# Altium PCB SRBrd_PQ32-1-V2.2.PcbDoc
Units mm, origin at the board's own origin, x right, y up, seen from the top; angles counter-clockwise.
Board outline 34 x 34.84 mm, 4 copper layers (Top Layer, Signal Layer 1, Signal Layer 2, Bottom Layer), stack 1.02 mm thick; 24 components, 9 nets, 205 pads, 210 vias.
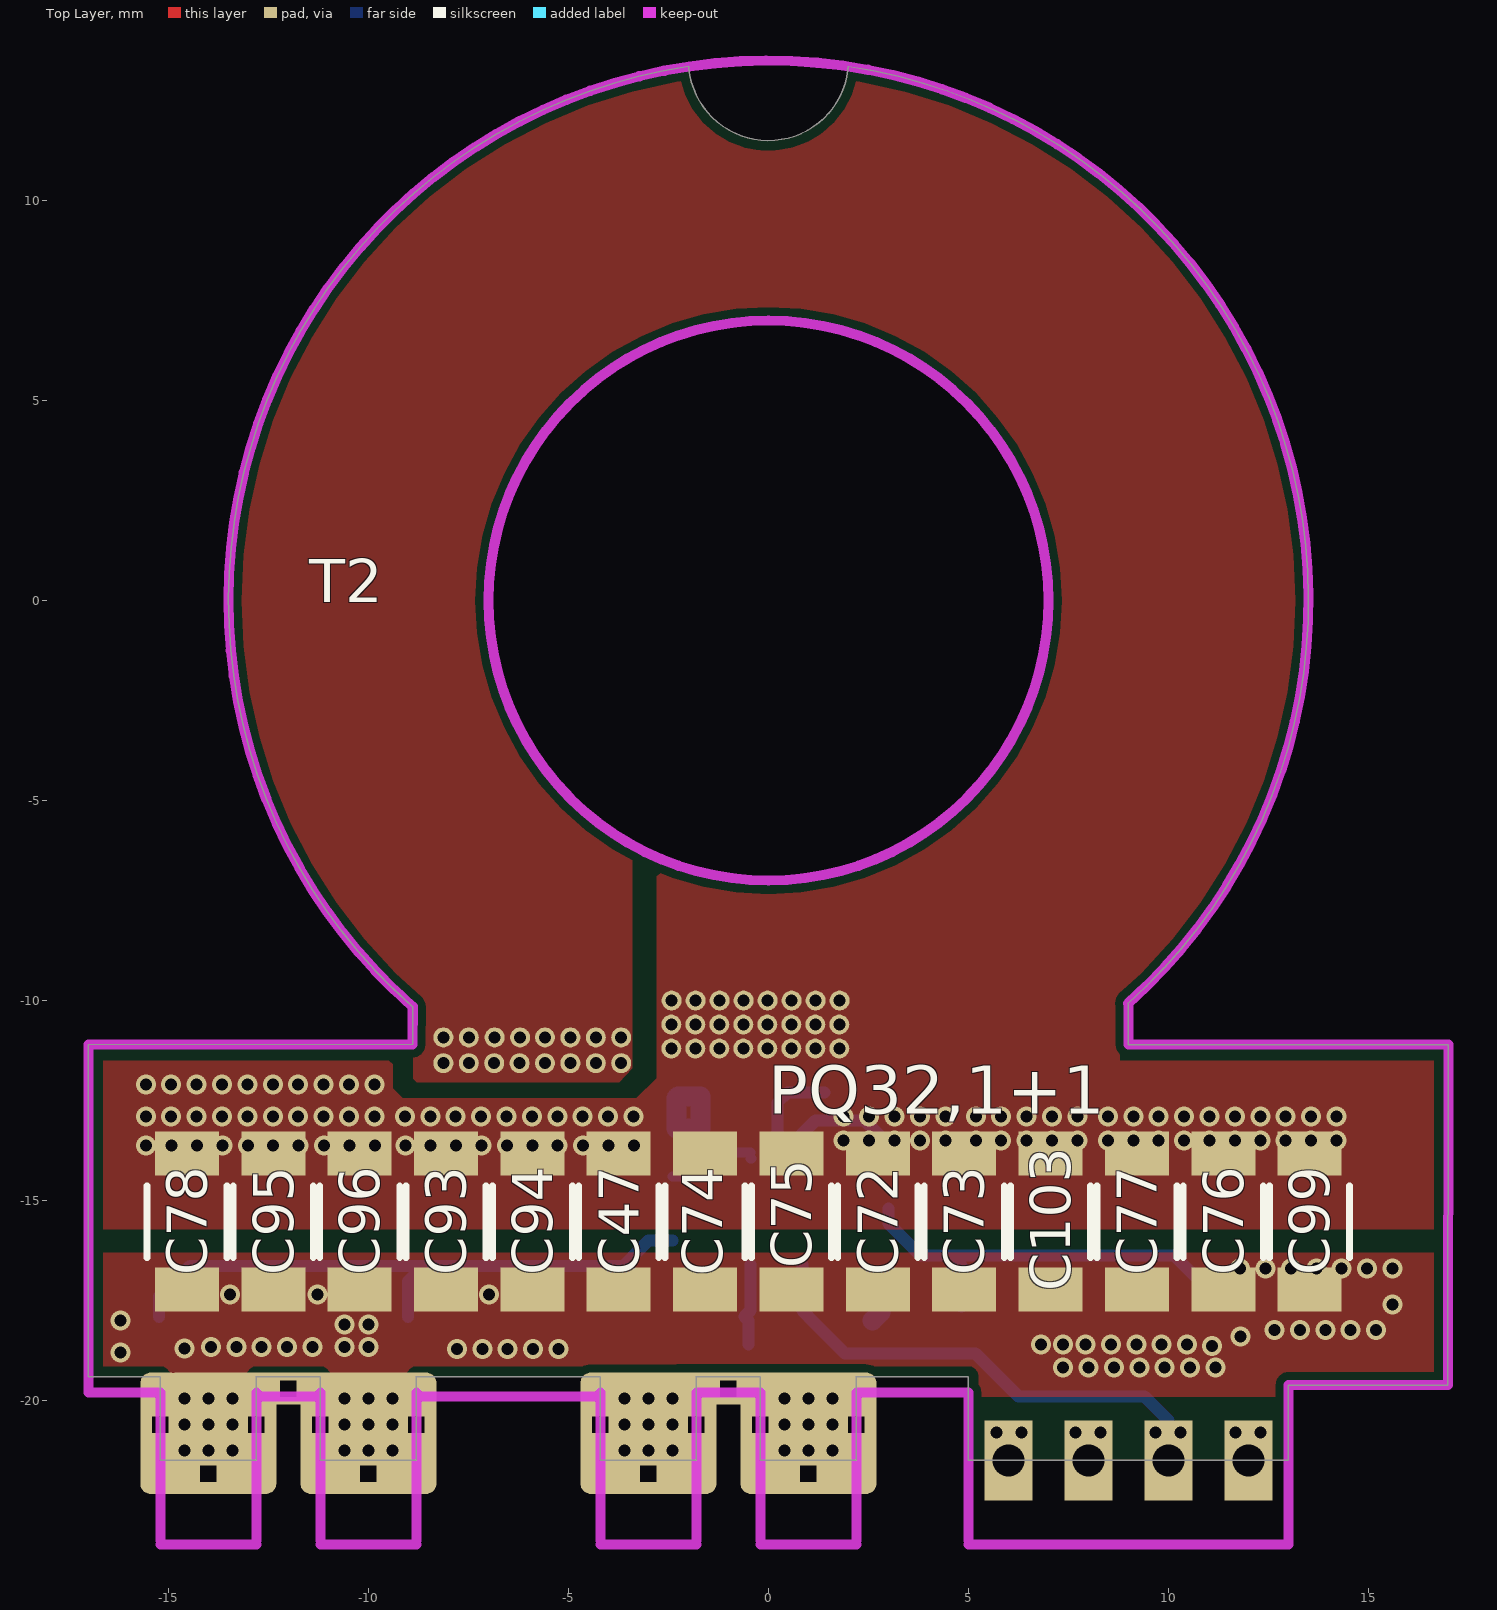
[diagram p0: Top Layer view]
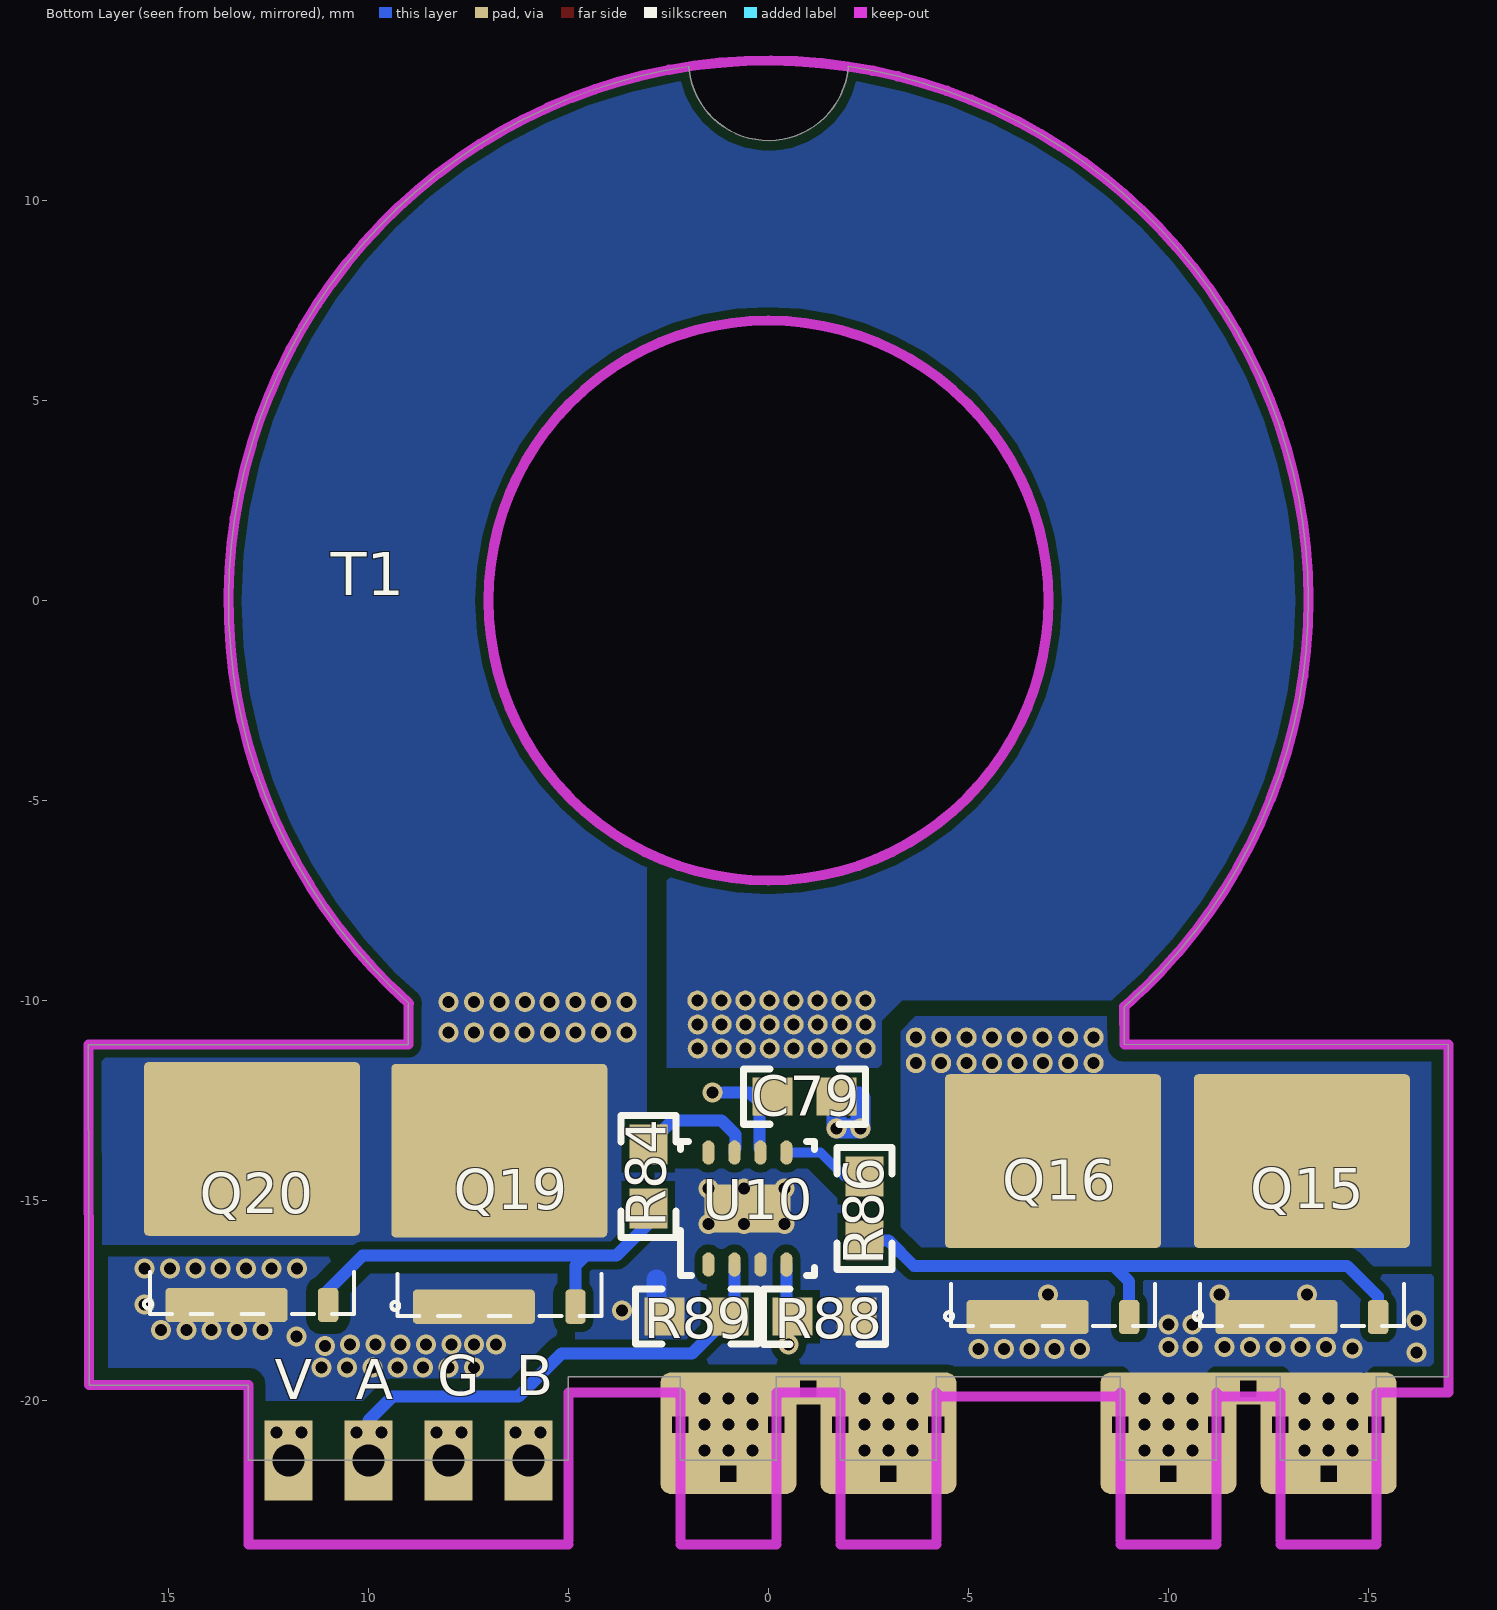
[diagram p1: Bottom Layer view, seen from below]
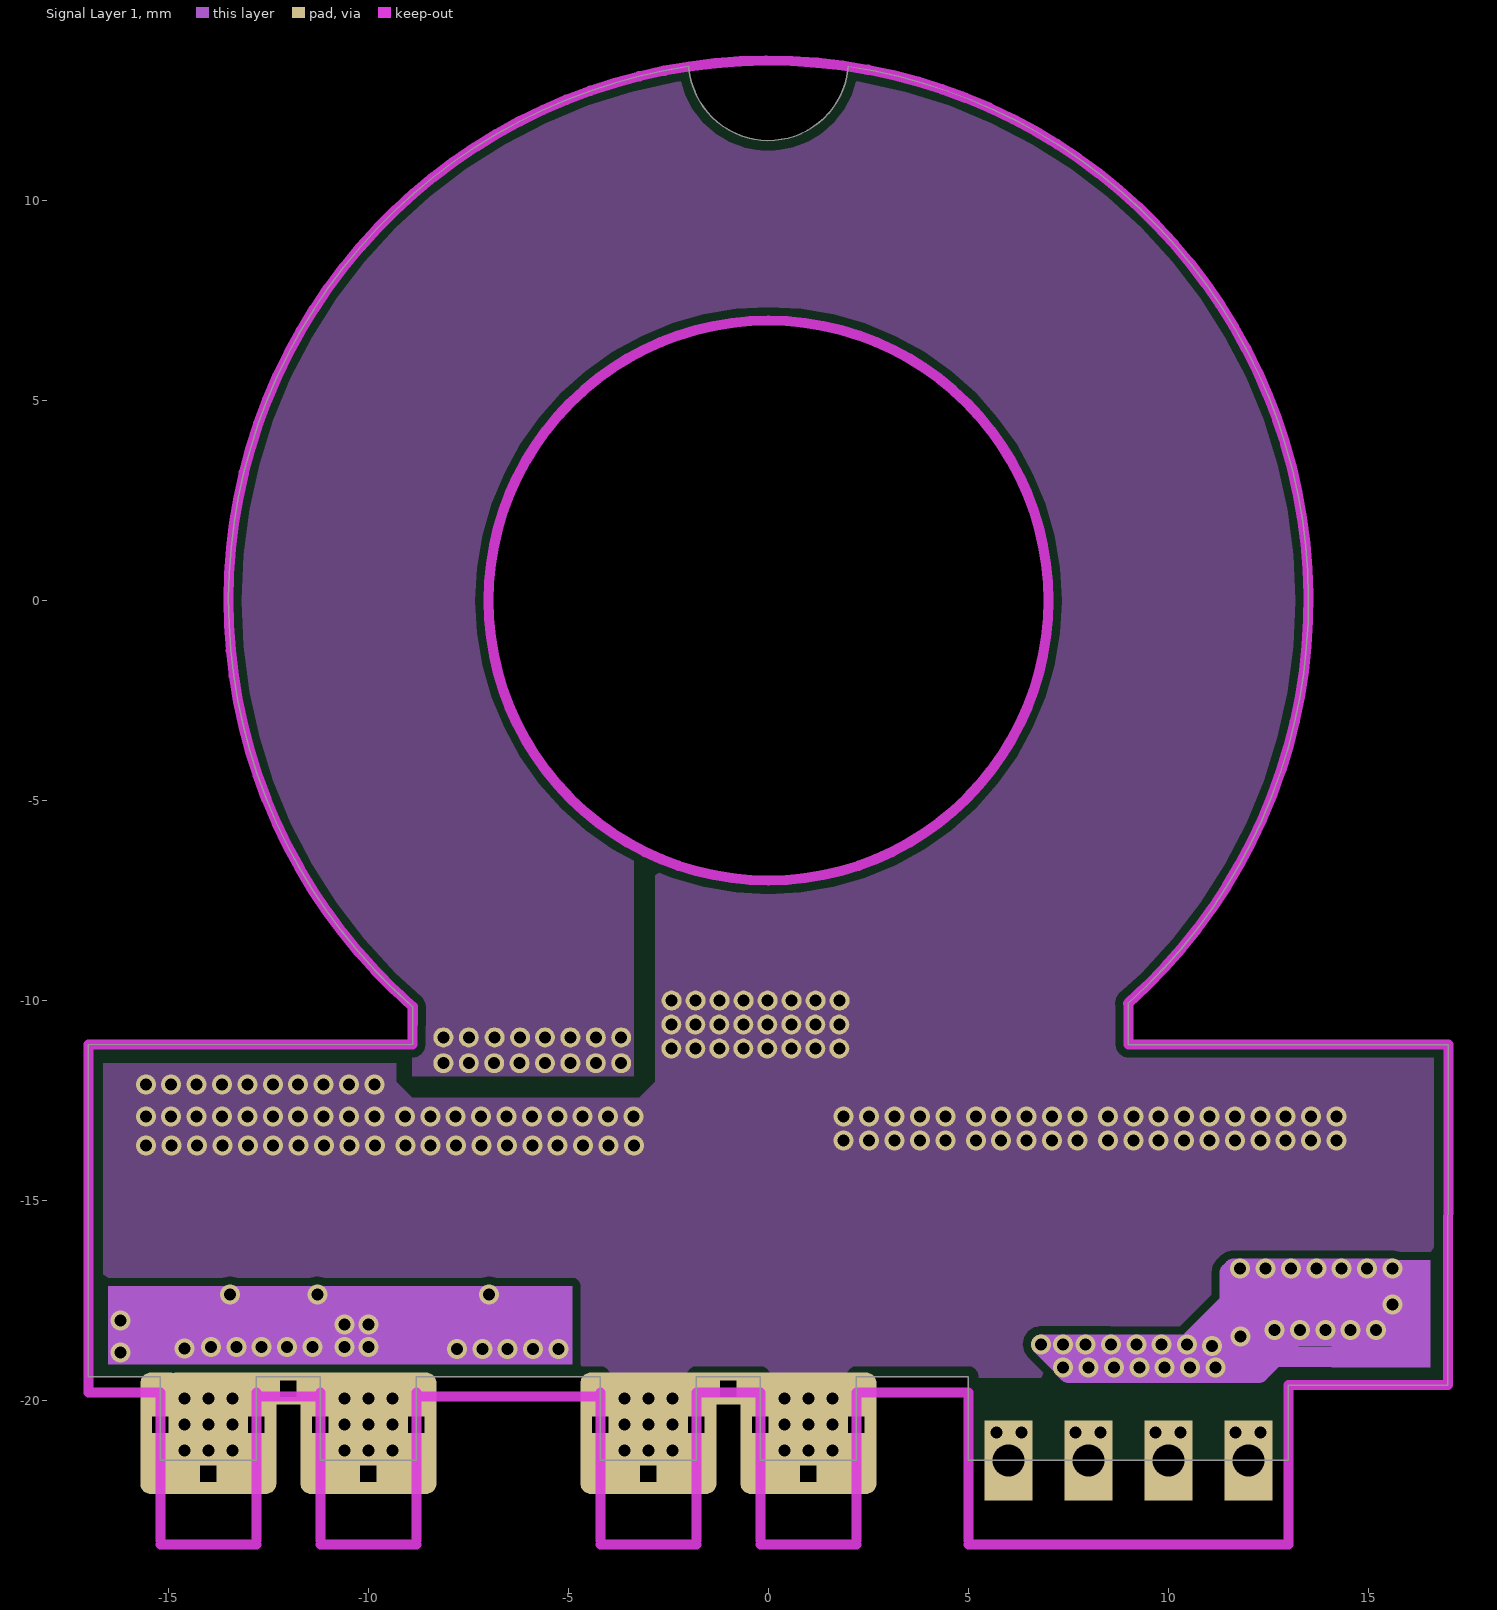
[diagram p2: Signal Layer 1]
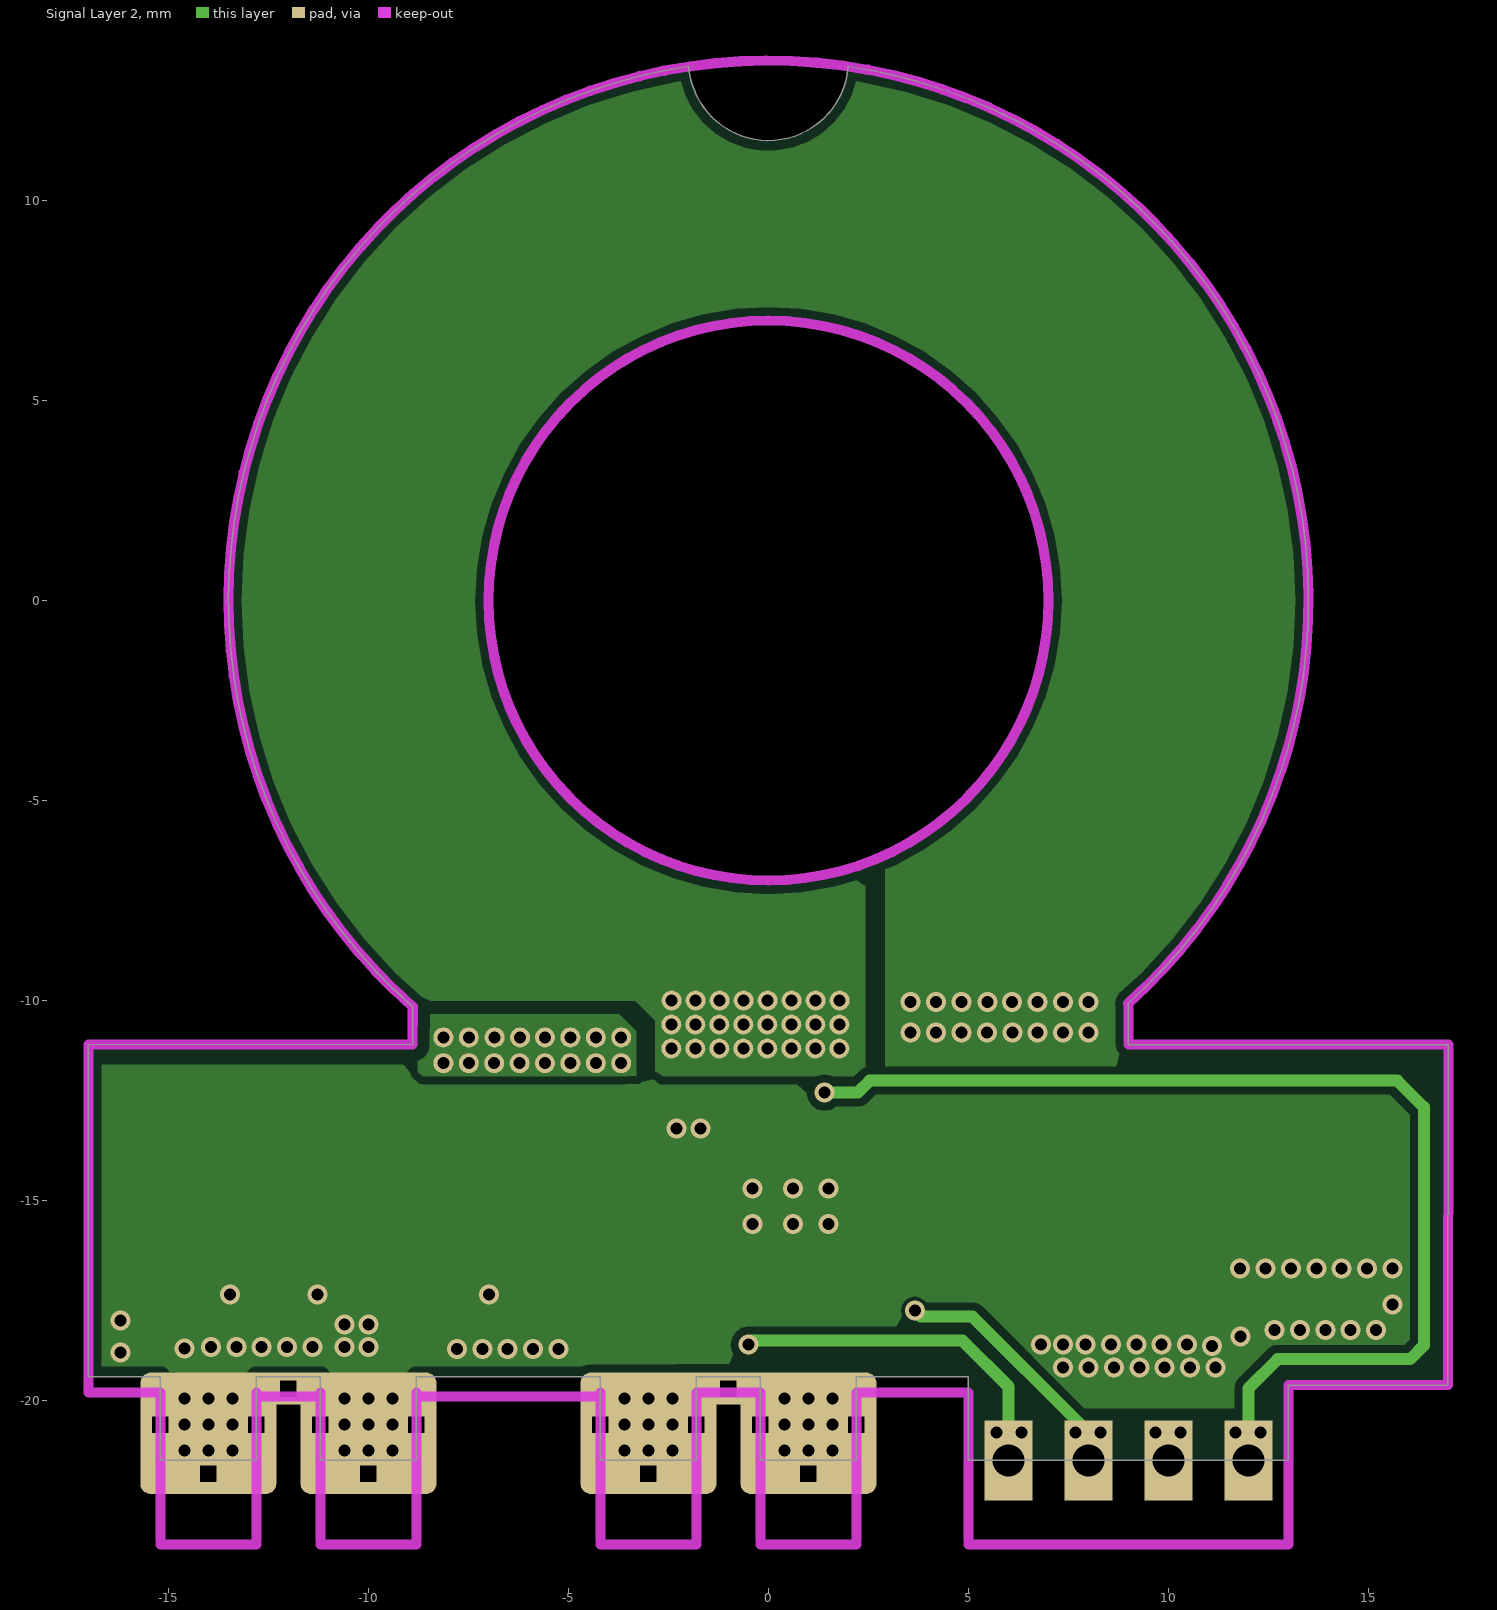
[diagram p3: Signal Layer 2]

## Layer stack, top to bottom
Top Solder: solder mask 0.0102, Solder Resist, Dk 3.5
Top Layer: signal copper 0.105
Dielectric 1: core 0.1, FR-4, Dk 4.2
Signal Layer 1: signal copper 0.105
Dielectric 3: prepreg 0.4, Dk 4.2
Signal Layer 2: signal copper 0.105
Dielectric 2: core 0.1, Dk 4.2
Bottom Layer: signal copper 0.105
Bottom Solder: solder mask 0.0102, Solder Resist, Dk 3.5

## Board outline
-15.2,-21.488 -12.8,-21.488 -12.8,-19.4 -11.2,-19.4 -11.2,-21.488 -8.8,-21.488 -8.8,-19.4 -4.2,-19.4 -4.2,-21.488 -1.8,-21.488 -1.8,-19.4 -0.2,-19.4 -0.2,-21.488 2.2,-21.488 2.2,-19.4 5,-19.4 5,-21.488 13,-21.488 13,-19.613 16.987,-19.613 17,-11.1 9,-11.1 9,-10.1 8.987,-10.074 ccw(c0,0) 1.999,13.351 1.986,13.264 cw(c0,13.5) -1.99,13.3 -1.997,13.351 ccw(c0,0) -8.925,-10.129 -8.895,-10.16 -8.895,-11.095 -17,-11.1 -17,-19.4 -15.2,-19.4

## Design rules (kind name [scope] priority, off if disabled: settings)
BoardOutlineClearance [All] p1: gap=0.254 ignorepadtopadclearanceinfootprint=FALSE except(0: Arc-SplitContinuation Track-SplitContinuation SMDPad-SplitContinuation THPad-SplitContinuation Via-SplitContinuation Fill-SplitContinuation Poly-SplitContinuation Region-SplitContinuation Text-SplitContinuation)
Clearance [All] p1: gap=0.2 ignorepadtopadclearanceinfootprint=FALSE
ComponentClearance [All] p1 off: gap=0.254 collisioncheckmode=3 verticalgap=0.254 showdistances=FALSE
Height [All] p1 off: minheight=0 maxheight=25.4 prefheight=12.7
HoleSize [All] p1: absolutevalues=TRUE maxlimit=30 minlimit=0.025 maxpercent=80.000 minpercent=20.000
MinimumSolderMaskSliver [All] p1: minsoldermaskwidth=0
PolygonConnect [All] p1: connectstyle=Direct reliefconductorwidth=0.254 reliefentries=4 polygonreliefangle="90 Angle" airgapwidth=0.254
RoutingVias [All] p1: holewidth=0.711 width=1.27 viastyle="Through Hole" minholewidth=0.711 minwidth=1.27 maxholewidth=0.711 maxwidth=1.27
SilkToSilkClearance [All] p1: silktosilkclearance=0
SilkToSolderMaskClearance [IsPad] p1: minsilkscreentomaskgap=0.1 clearancetoexposedcopper=TRUE
SolderMaskExpansion [All] p1: expansion=0.102 istentingtop=FALSE
Width [All] p1: maxlimit=2.54 minlimit=0.152 preferedwidth=0.254
24 further rules are at their usual default settings.

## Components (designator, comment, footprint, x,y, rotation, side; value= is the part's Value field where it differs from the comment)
C47 "GMK316AB7106KL-TR" 1206_190 -3.744,-15.529 r270 top value=10uF
C72 "GMK316AB7106KL-TR" 1206_190 2.733,-15.529 r270 top value=10uF
C73 "GMK316AB7106KL-TR" 1206_190 4.892,-15.529 r270 top value=10uF
C74 "GMK316AB7106KL-TR" 1206_190 -1.585,-15.529 r270 top value=10uF
C75 "GMK316AB7106KL-TR" 1206_190 0.574,-15.529 r270 top value=10uF
C76 "GMK316AB7106KL-TR" 1206_190 11.369,-15.529 r270 top value=10uF
C77 "GMK316AB7106KL-TR" 1206_190 9.21,-15.529 r90 top value=10uF
C78 "GMK316AB7106KL-TR" 1206_190 -14.539,-15.529 r90 top value=10uF
C79 "UMK107AB7105KA-T" 0603 -0.9,-12.4 r0 bottom value=1uF
C93 "GMK316AB7106KL-TR" 1206_190 -8.062,-15.529 r90 top value=10uF
C94 "GMK316AB7106KL-TR" 1206_190 -5.903,-15.529 r90 top value=10uF
C95 "GMK316AB7106KL-TR" 1206_190 -12.38,-15.529 r90 top value=10uF
C96 "GMK316AB7106KL-TR" 1206_190 -10.221,-15.529 r90 top value=10uF
C99 "GMK316AB7106KL-TR" 1206_190 13.528,-15.529 r270 top value=10uF
C103 "GMK316AB7106KL-TR" 1206_190 7.051,-15.529 r90 top value=10uF
Q15 "CSD18509Q5B" DNK0008A -13.335,-15.092 r90 bottom value=40V
Q16 "CSD18509Q5B" DNK0008A -7.112,-15.092 r90 bottom value=40V
Q19 "CSD18509Q5B" DNK0008A 6.731,-14.833 r90 bottom value=40V
Q20 "CSD18509Q5B" DNK0008A 12.913,-14.791 r90 bottom value=40V
R84 "ERJ-3RQF2R2V" 0603 3,-14.4 r270 bottom value=2.20
R86 "ERJ-3RQF2R2V" 0603 -2.4,-15.2 r270 bottom value=2.20
R88 "ERJ-3EKF1002V" 0603 -1.4,-17.9 r0 bottom value=10.0k
R89 "ERJ-3EKF1002V" 0603 1.8,-17.9 r180 bottom value=10.0k
U10 "UCC27524DSDR" DSD0008D 0.525,-15.2 r90 bottom

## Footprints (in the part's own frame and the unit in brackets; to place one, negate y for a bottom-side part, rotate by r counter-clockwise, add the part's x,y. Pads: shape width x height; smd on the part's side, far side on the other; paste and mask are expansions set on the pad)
0603 [mm] "0603 from SM-752 data"
  rect 1x0.95 smd: 1(-0.8,0) 2(0.8,0)
  silkscreen extent -1.52,-0.69 1.52,0.69, body extent -0.87,-0.47 0.87,0.47, height 1
1206_190 [mm] "1206_190"
  rect 1.1x1.6 smd: 1(-1.7,0) 2(1.7,0)
  silkscreen extent -0.9,-1 0.9,1, body extent -1.75,-0.95 1.75,0.95, height 1.9
DNK0008A [mm] "SON, 8-Leads, Body 5x6mm"
  rrect39% 0.86x0.51 smd paste-0.05 mask-0.05: 1(-2.82,1.905) 3(-2.82,-0.635) 4(-2.82,-1.905) 5(2.82,-1.905) 6(2.82,-0.635) 7(2.82,0.635) 8(2.82,1.905)
  rrect39% 0.86x3 smd paste-0.05 mask-0.05: 2(-2.82,0.635)
  rrect40% 0.25x0.555 on Bottom Solder: 9(-0.83,-2.372) 9(-0.83,2.372)
  rrect40% 0.25x0.555 on Bottom Paste: 9(-0.83,-2.372) 9(-0.83,2.372)
  rrect11% 0.95x1.13 on Bottom Paste: 9(-0.535,-1.33) 9(-0.535,0) 9(-0.535,1.33) 9(0.615,-1.33) 9(0.615,0) 9(0.615,1.33) 9(1.765,-1.33) 9(1.765,0) 9(1.765,1.33)
  rrect3% 3.58x4 on Bottom Solder: 9(0.75,0)
  rrect5% 4.34x5.4 smd paste-3 mask-3: 9(1.08,0)
  silkscreen extent -3.05,-2.55 -2,2.7, body extent -3.05,-2.55 3.05,2.55, height 1.06
DSD0008D [mm]
  oval 0.6x0.31 smd: 1(-1.4,0.975) 2(-1.4,0.325) 3(-1.4,-0.325) 4(-1.4,-0.975) 5(1.4,-0.975) 6(1.4,-0.325) 7(1.4,0.325) 8(1.4,0.975)
  rect 1.2x2.15 smd paste-0.6: 9(0,0)
  silkscreen extent -1.68,-1.68 1.68,1.68, body extent -1.57,-1.57 1.57,1.57, height 0.8

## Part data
C47 C72 C73 C74 C75 C76 C77 C78 C93 C94 C95 C96 C99 C103: library part CMP-0008822-2, "CAP, CERM, 10 uF, 35 V, +/- 10%, X7R, 1206_190", Cap_Case=1206, Manufacturer="Taiyo Yuden", Supplier Part Number 1=587-3007-1-ND, TempCo=X7R, Tolerance_%=10%, Value1=Unknown, Value2=35V, ValueDisplayed=10uF
C79: library part CMP-0007508-5, "CAP, CERM, 1 uF, 50 V, +/- 10%, X7R, 0603", Cap_Case=0603, Manufacturer="Taiyo Yuden", Supplier Part Number 1=587-3247-1-ND, TempCo=X7R, Tolerance_%=10%, Value1=Unknown, Value2=50V, ValueDisplayed=1uF
Q15 Q16 Q19 Q20: library part CMP-0000709-2, "MOSFET, N-CH, 40 V, 100 A, DNK0008A (VSON-CLIP-8)", Alternate Manufacturer=None, Manufacturer="Texas Instruments", Supplier Part Number 1=296-41075-1-ND, Value1=0.001, Value2="150 nC"
R84: library part CMP-0022711-2, "RES, 2.20, 1%, 0.1 W, 0603", Manufacturer=Panasonic, Power_W=100mW, Supplier Part Number 1=P2.2AJCT-ND, TempCo="200 ppm/C", Tolerance_%=1%, Value2=0.1W, Value_Code=2R20, ValueDisplayed=1R0
R86: library part CMP-0022711-2, "RES, 1ohm 1%, 0.1 W, 0603", Manufacturer=Panasonic, Power_W=100mW, TempCo="200 ppm/C", Tolerance_%=1%, Value2=0.1W, Value_Code=1R, ValueDisplayed=1R0
R88 R89: library part CMP-0022684-3, "RES, 10.0 k, 1%, 0.1 W, 0603", Manufacturer=Panasonic, Power_W=100mW, Supplier Part Number 1=P10.0KHCT-ND, TempCo="100 ppm/C", Tolerance_%=1%, Value2=0.1W, Value_Code=10k0, ValueDisplayed=10.0k
U10: library part CMP-0066952-1, "Dual, 5A, High-Speed Low-Side Power MOSFET Driver, DSD0008D (WSON-8)", Alternate Manufacturer="Texas Instruments", Alternate PartNumber=UCC27524DSDT

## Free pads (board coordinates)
  rect 1.2x2 hole 0.8: 1(12,-21.5) 2(10,-21.5) 3(8,-21.5) 4(6,-21.5)
  rrect50% 3.4x2.6 hole 0.3: 5(-3,-20.6) 5(1,-20.6) 6(-10,-20.6)
  rrect50% 1x2.6 hole 0.4 square: 6(-15.2,-20.6) 6(-12.8,-20.6) 6(-11.2,-20.6) 6(-8.8,-20.6) 6(-4.2,-20.6) 6(-1.8,-20.6) 6(-0.2,-20.6) 6(2.2,-20.6)
  rrect50% 3.4x1 hole 0.4 square: 6(-14.006,-21.834) 6(-10,-21.834) 6(-3,-21.834) 6(1,-21.834)
  rrect50% 3x2.6 hole 0.3: 6(-14,-20.6)
  rrect50% 3x0.8 hole 0.4 square: 6(-12,-19.7) 6(-1,-19.7)
  round 0 hole 14: 7(0,0)
  round 0.5 hole 0.3 mask+0.102: 11(-8.128,-10.922) 11(-7.493,-10.922) 11(-6.858,-11.566) 11(-6.846,-10.922) 11(-6.21,-10.922) 11(-5.588,-11.566) 11(-5.588,-10.922) 11(-3.683,-11.566) 11(-2.431,-10.6) 11(-1.231,-10.6) 11(-0.031,-10.6) 11(1.169,-10.6) 12(-4.318,-11.566) 12(-4.318,-10.922) 12(-2.431,-11.2) 12(-2.422,-10) 12(-1.831,-11.2) 12(-1.831,-10.6) 12(-1.822,-10) 12(-1.231,-11.2) 12(-1.222,-10) 12(-0.631,-11.2) 12(-0.631,-10.6) 12(-0.622,-10) 12(-0.031,-11.2) 12(-0.022,-10) 12(0.569,-11.2) 12(0.569,-10.6) 12(0.578,-10) 12(1.169,-11.2) 12(1.178,-10) 12(1.769,-11.2) 12(1.769,-10.6) 12(1.778,-10) 13(-8.128,-11.566) 13(-3.683,-10.922) 14(-7.493,-11.566) 14(-6.223,-11.566) 14(-4.953,-11.566) 14(-4.953,-10.922) 15(-6.858,-11.566) 15(-5.588,-11.566) 15(-4.318,-11.566)

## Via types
v1: diameter 0.5, hole 0.3, Top Layer to Bottom Layer, tented both sides, 93 vias
v2: diameter 0.5, hole 0.3, Top Layer to Signal Layer 1, tented both sides, 90 vias
v3: diameter 0.5, hole 0.3, Signal Layer 2 to Bottom Layer, tented both sides, 27 vias

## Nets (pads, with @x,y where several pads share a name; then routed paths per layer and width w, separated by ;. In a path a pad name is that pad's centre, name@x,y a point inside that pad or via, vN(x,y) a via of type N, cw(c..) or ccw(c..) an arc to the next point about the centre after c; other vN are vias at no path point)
5Vcc: C79.2 pad.1 U10.6 | length 30.6
  Signal Layer 2 w0.3: v3(1.4,-12.3) 2.233,-12.3 2.53,-12.003 15.719,-12.003 16.383,-12.667 16.383,-18.622 16.042,-18.963 12.731,-18.963 12,-19.694 pad.1 pad.1@12,-21.7
  Bottom Layer w0.3: U10.6@0.22,-13.7 0.22,-12.558 0.478,-12.3 v3(1.4,-12.3)
  other v1: 11.676,-20.8 12.3,-20.8
12Vs: C47.1 C72.1 C73.1 C74.1 C75.1 C76.1 C77.2 C78.2 C93.2 C94.2 C95.2 C96.2 C99.1 C103.2 pad.5 pad.6@1,-21.834 pad.6@2.2,-20.6 pad.6@-0.2,-20.6 pad.6@-1,-19.7 pad.6@-1.8,-20.6 pad.6@-3,-21.834 pad.6@-4.2,-20.6 pad.11 pad.12 pad.13 pad.14 pad.15 Q15.5 Q15.6 Q15.7 Q15.8 Q15.9@-13.335,-14.012 Q16.5 Q16.6 Q16.7 Q16.8 Q16.9@-7.112,-14.012 Q19.5 Q19.6 Q19.7 Q19.8 Q19.9@6.731,-13.753 Q20.5 Q20.6 Q20.7 Q20.8 Q20.9@12.913,-13.711
  other v1: -3.6,-21.245 -3,-21.245 -2.4,-21.245 0.4,-21.245 1,-21.245 1.6,-21.245 -3.6,-20.6 -3,-20.6 -2.4,-20.6 0.4,-20.6 1,-20.6 1.6,-20.6 -3.6,-19.955 -3,-19.955 -2.4,-19.955 0.4,-19.955 1,-19.955 1.6,-19.955
  other v2: -15.557,-13.627 -14.922,-13.627 -14.287,-13.627 -13.652,-13.627 -13.017,-13.627 -12.382,-13.627 -11.747,-13.627 -11.112,-13.627 -10.477,-13.627 -9.842,-13.627 -9.08,-13.627 -8.445,-13.627 -7.81,-13.627 -7.175,-13.627 -6.54,-13.627 -5.905,-13.627 -5.27,-13.627 -4.635,-13.627 -4,-13.627 -3.365,-13.627 1.881,-13.5 2.516,-13.5 3.151,-13.5 3.786,-13.5 4.421,-13.5 5.183,-13.5 5.818,-13.5 6.453,-13.5 7.088,-13.5 7.723,-13.5 8.485,-13.5 9.12,-13.5 9.755,-13.5 10.39,-13.5 11.025,-13.5 11.66,-13.5 12.295,-13.5 12.93,-13.5 13.565,-13.5 14.2,-13.5 -15.567,-12.9 -14.932,-12.9 -14.297,-12.9 -13.662,-12.9 -13.027,-12.9 -12.392,-12.9 -11.757,-12.9 -11.122,-12.9 -10.487,-12.9 -9.852,-12.9 -9.09,-12.9 -8.455,-12.9 -7.82,-12.9 -7.185,-12.9 -6.55,-12.9 -5.915,-12.9 -5.28,-12.9 -4.645,-12.9 -4.01,-12.9 -3.375,-12.9 1.881,-12.9 2.516,-12.9 3.151,-12.9 3.786,-12.9 4.421,-12.9 5.183,-12.9 5.818,-12.9 6.453,-12.9 7.088,-12.9 7.723,-12.9 8.485,-12.9 9.12,-12.9 9.755,-12.9 10.39,-12.9 11.025,-12.9 11.66,-12.9 12.295,-12.9 12.93,-12.9 13.565,-12.9 14.2,-12.9 -15.567,-12.1 -14.932,-12.1 -14.297,-12.1 -13.662,-12.1 -13.027,-12.1 -12.392,-12.1 -11.757,-12.1 -11.122,-12.1 -10.487,-12.1 -9.852,-12.1
  other v3: 3.556,-10.795 4.191,-10.795 4.826,-10.795 5.461,-10.795 6.096,-10.795 6.731,-10.795 7.366,-10.795 8.001,-10.795 3.556,-10.033 4.191,-10.033 4.826,-10.033 5.473,-10.033 6.087,-10.033 6.731,-10.033 7.366,-10.033 8.001,-10.033
NetR84_1: R84.1 U10.7 | length 3
  Bottom Layer w0.3: U10.7@0.825,-13.7 0.825,-13.349 1.174,-13 2.4,-13 R84.1 ; U10.7 U10.7@0.85,-13.7
NetR86_1: R86.1 U10.5 | length 2.2
  Bottom Layer w0.254: R86.1 -1.9,-14.4 -1.3,-13.8 U10.5 ; U10.5@-0.45,-13.945 U10.5@-0.426,-13.945
SGND1: C47.2 C72.2 C73.2 C74.2 C75.2 C76.2 C77.1 C78.1 C79.1 C93.1 C94.1 C95.1 C96.1 C99.2 C103.1 pad.3 pad.6@-8.8,-20.6 pad.6@-10,-20.6 pad.6@-10,-21.834 pad.6@-11.2,-20.6 pad.6@-12,-19.7 pad.6@-12.8,-20.6 pad.6@-14,-20.6 pad.6@-14.006,-21.834 pad.6@-15.2,-20.6 Q15.1 Q15.2 Q15.3 Q16.1 Q16.2 Q16.3 Q19.1 Q19.2 Q19.3 Q20.1 Q20.2 Q20.3 R88.1 R89.1 U10.3 U10.9 | length 51.7
  Signal Layer 1 w0.5: v1(-16.2,-18) v1(-16.2,-18.8) v1@-16.1,-18.7 ; v1@7.341,-18.974 7.363,-18.974 7.367,-18.974 7.922,-18.978 8.003,-18.979 8.556,-18.983 8.637,-18.984 9.191,-18.988 9.272,-18.989 9.826,-18.993 9.907,-18.994 10.461,-18.998 10.542,-18.999 v1@11.082,-19.003 ; v1(10.464,-18.605) v1@10.469,-18.6 ; 11.83,-19.177 v1(11.176,-19.177) v1@11.124,-19.177 ; v1(7.366,-19.177) 7.495,-19.306 v1@11.124,-19.306 ; v1(7.366,-19.177) v1(8.001,-19.177) v1(8.636,-19.177) v1(9.271,-19.177) v1(9.906,-19.177) v1(10.541,-19.177) v1@11.124,-19.177 ; v1(7.366,-19.177) 7.366,-19.152 v1(6.807,-18.593) v1(7.366,-18.593) 7.924,-18.595 8.559,-18.596 9.194,-18.597 9.829,-18.599 10.464,-18.6 v1@10.469,-18.6 ; v1@10.469,-18.6 11.523,-17.546 ; v1@10.469,-18.6 11.05,-18.6 v1(11.087,-18.637) ; v1@11.082,-19.003 v1@11.124,-18.961 ; v1@11.082,-19.003 v1@11.124,-19.003 ; v1(11.087,-18.637) 11.753,-18.637 11.8,-18.59 v1(11.8,-18.4) ; v1(11.087,-18.637) 11.324,-18.4 ; v1(11.087,-18.637) 11.124,-18.674 v1@11.124,-18.961 ; v1@11.124,-19.306 12.257,-19.306 12.657,-18.906 ; v1@11.124,-19.306 v1@11.124,-19.177 ; v1@11.124,-19.177 v1@11.124,-19.003 ; v1@11.124,-19.003 12.022,-19.003 v1@12.625,-18.4 ; v1@11.124,-19.003 v1@11.124,-18.961 ; 11.324,-18.4 v1(11.8,-18.4) ; 11.324,-18.4 11.523,-18.201 11.523,-17.933 ; 11.523,-17.933 11.8,-18.21 v1(11.8,-18.4) ; 11.523,-17.933 11.523,-17.546 ; 11.523,-17.546 11.523,-16.8 ; 11.523,-16.8 11.99,-17.267 11.8,-17.457 v1(11.8,-18.4) ; 11.523,-16.8 11.623,-16.7 v1(11.79,-16.7) v1(12.425,-16.7) v1(13.06,-16.7) v1(13.695,-16.7) v1(14.33,-16.7) v1(14.965,-16.7) v1(15.6,-16.7) v1(15.6,-17.6) 15.6,-17.912 15.165,-18.347 v1@15.165,-18.4 ; v1(11.8,-18.4) v1@12.625,-18.4 ; v1@12.625,-18.4 v1@13.163,-18.4 ; 12.657,-18.906 14.659,-18.906 v1@15.165,-18.4 ; 12.657,-18.906 v1@13.163,-18.4 ; v1@13.163,-18.4 v1@15.165,-18.4
  Signal Layer 2 w0.3: v3(3.658,-17.755) 3.804,-17.901 5.1,-17.901 pad.3@7.777,-20.579
  Bottom Layer w0.5: R89.1@2.6,-18 2.8,-17.8 2.8,-16.972 ; v3(-2.3,-13.2) v3(-1.7,-13.2) C79.1 -1.705,-12.395 -2.261,-12.395 -2.3,-12.435 v3(-2.3,-13.2)
  other v1: -14.6,-21.245 -14,-21.245 -13.4,-21.245 -10.6,-21.245 -10,-21.245 -9.4,-21.245 7.676,-20.8 8.3,-20.8 -14.6,-20.6 -14,-20.6 -13.4,-20.6 -10.6,-20.6 -10,-20.6 -9.4,-20.6 -14.6,-19.955 -14,-19.955 -13.4,-19.955 -10.6,-19.955 -10,-19.955 -9.4,-19.955 -7.791,-18.716 -7.156,-18.716 -6.521,-18.716 -5.886,-18.716 -5.251,-18.716 -14.6,-18.7 -13.94,-18.662 -13.305,-18.662 -12.67,-18.662 -12.035,-18.662 -11.4,-18.662 -10.6,-18.662 -10,-18.662 7.924,-18.605 8.559,-18.605 9.194,-18.605 9.829,-18.605 12.649,-18.237 13.284,-18.237 13.919,-18.237 14.554,-18.237 15.189,-18.237 -10.6,-18.1 -10,-18.1 -13.462,-17.348 -11.278,-17.348 -6.985,-17.348
  other v3: -0.405,-15.589 0.611,-15.589 1.5,-15.589 -0.405,-14.7 0.611,-14.7 1.5,-14.7
SR1A: pad.2 R89.2 U10.2 | length 12.6
  Bottom Layer w0.3: U10.2 0.85,-17.75 R89.2 ; R89.2@1,-17.911 1.914,-18.825 5.175,-18.825 6.25,-19.9 9.4,-19.9 pad.2@10,-20.5 ; pad.2@9.976,-20.735 pad.2@9.976,-20.7 ; pad.2@10,-21.7 pad.2 pad.2@10,-20.535
  other v1: 9.676,-20.8 10.3,-20.8
SR1B: pad.4 R88.2 U10.4 | length 11
  Signal Layer 2 w0.3: v3(-0.5,-18.6) -0.401,-18.501 4.851,-18.501 6,-19.65 pad.4
  Bottom Layer w0.3: v3(-0.5,-18.6) -0.5,-18 R88.2 -0.45,-17.75 U10.4
  other v1: 5.7,-20.8 6.324,-20.8
VG_SR1A: Q19.4 Q20.4 R84.2 | length 10.8
  Bottom Layer w0.3: R84.2 3,-15.573 3.8,-16.373 4.571,-16.373 ; Q19.4 4.826,-16.628 4.571,-16.373 ; Q20.4 11.008,-17.237 10.145,-16.373 4.571,-16.373
VG_SR1B: Q15.4 Q16.4 R86.2 | length 15.4
  Bottom Layer w0.3: Q15.4 -15.24,-17.404 -14.468,-16.632 -8.626,-16.632 ; Q16.4 -9.017,-17.023 -8.626,-16.632 ; R86.2 -3,-16 -3.632,-16.632 -8.626,-16.632
pads on no net: Q15.9@-10.963,-15.922 Q15.9@-12.005,-13.327 Q15.9@-12.005,-14.477 Q15.9@-12.005,-15.627 Q15.9@-13.335,-13.327 Q15.9@-13.335,-14.342 Q15.9@-13.335,-14.477 Q15.9@-13.335,-15.627 Q15.9@-14.665,-13.327 Q15.9@-14.665,-14.477 Q15.9@-14.665,-15.627 Q15.9@-15.707,-15.922 Q16.9@-4.74,-15.922 Q16.9@-5.782,-13.327 Q16.9@-5.782,-14.477 Q16.9@-5.782,-15.627 Q16.9@-7.112,-13.327 Q16.9@-7.112,-14.342 Q16.9@-7.112,-14.477 Q16.9@-7.112,-15.627 Q16.9@-8.442,-13.327 Q16.9@-8.442,-14.477 Q16.9@-8.442,-15.627 Q16.9@-9.484,-15.922 Q19.9@4.359,-15.663 Q19.9@5.401,-13.068 Q19.9@5.401,-14.218 Q19.9@5.401,-15.368 Q19.9@6.731,-13.068 Q19.9@6.731,-14.083 Q19.9@6.731,-14.218 Q19.9@6.731,-15.368 Q19.9@8.061,-13.068 Q19.9@8.061,-14.218 Q19.9@8.061,-15.368 Q19.9@9.103,-15.663 Q20.9@10.541,-15.621 Q20.9@11.583,-13.026 Q20.9@11.583,-14.176 Q20.9@11.583,-15.326 Q20.9@12.913,-13.026 Q20.9@12.913,-14.041 Q20.9@12.913,-14.176 Q20.9@12.913,-15.326 Q20.9@14.243,-13.026 Q20.9@14.243,-14.176 Q20.9@14.243,-15.326 Q20.9@15.286,-15.621 U10.1 U10.8

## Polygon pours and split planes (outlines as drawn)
SGND1 on Bottom Layer "SGND1_L04_P018" (solid, remove dead copper, pour order 18): 3.302,-17.785 3.302,-18.637 4.665,-20 16.51,-20 16.51,-16.373 4.714,-16.373
12Vs on Bottom Layer "12VS_L04_P012" (solid, remove dead copper, pour order 12): -16.764,-16.637 -16.764,-11.535 -8.9,-11.535 -8.9,-10.398 -3.668,-10.398 -3.302,-10.763 -3.302,-16.637
SGND1 on Bottom Layer "SGND1_L04_P022" (solid, remove dead copper, pour order 22): -16.637,-16.769 -16.637,-19.613 4.826,-19.613 4.826,-14.2 -0.987,-14.2 -3.556,-16.769
12Vs on Bottom Layer "12VS_L04_P032" (solid, remove dead copper, pour order 32): -8.91,-9.991 -3.341,-9.994 -2.833,-10.502 -2.833,-11.684 2.54,-11.684 2.54,-6.096 3.048,-6.096 3.048,-16.1 17,-16.1 17,-11.1 9,-11.1 9,-10 13.5,-5.5 13.5,5.5 5.4,13.6 -5.4,13.6 -13.5,5.5 -13.5,-5.4 -10.6,-8.3 -10.6,-8.5
SGND1 on Top Layer "SGND1_L01_P046" (solid, remove dead copper, pour order 46): 5.1,-19.9 13,-19.9 13,-19.5 16.637,-19.5 16.637,-16.3 -16.637,-16.3 -16.637,-19.5 5.1,-19.5
12Vs on Top Layer "Signal Layer 2-No Net" (solid, remove dead copper, pour order 36): -16.637,-15.72 16.637,-15.72 16.637,-11.499 8.788,-11.499 8.788,-10.212 13.5,-5.5 13.5,5.5 5.4,13.6 -5.4,13.6 -13.5,5.5 -13.5,-5.4 -10.6,-8.3 -10.6,-8.5 -8.9,-10.2 -8.886,-11.327 -8.886,-12.042 -3.737,-12.042 -3.401,-11.692 -3.401,-5.842 -2.794,-5.842 -2.794,-11.938 -3.302,-12.446 -9.143,-12.446 -9.398,-12.191 -9.398,-11.499 -16.637,-11.499
SGND1 on Signal Layer 2 "SGND1_L03_P042" (solid, remove dead copper, pour order 42): 13.662,-19.563 17,-19.563 17,-13.825 14.775,-11.6 -16.764,-11.6 -16.764,-19.8 6.442,-19.8 6.442,-20.193 13.032,-20.193
12Vs on Signal Layer 2 "12VS_L03_P006" (solid, remove dead copper, pour order 6): -9.441,-10 -3.335,-10 -2.833,-10.503 -2.833,-11.898 2.413,-11.898 2.413,-6.096 2.921,-6.096 2.921,-11.767 9,-11.767 9,-10 13.5,-5.5 13.5,5.5 5.4,13.6 -5.4,13.6 -13.5,5.5 -13.5,-5.4 -10.6,-8.3 -10.6,-8.577
12Vs on Signal Layer 2 "Signal Layer 2-No Net" (solid, remove dead copper, pour order 26): -8.763,-10.338 -8.763,-11.898 -3.302,-11.898 -3.302,-10.763 -3.728,-10.338
no net on Top Paste "NONET_L-01_P-001" (solid): 6.403,-5.103 3.756,-7.75 -2.3,-7.75 -2.3,-10.795 2.431,-10.795 2.431,-10.417 3.148,-9.7 7.5,-9.7 9.25,-7.95
no net on Top Paste "NONET_L-01_P-001" (solid): -8.118,-9.078 -8.118,-10.763 -3.822,-10.763 -3.822,-7.95 -6.372,-5.4 -8.75,-5.4 -9.75,-6.4 -9.75,-7.446
12Vs on Signal Layer 1 "12VS_L02_P038" (solid, remove dead copper, pour order 38): -16.637,-19.431 16.637,-19.431 16.637,-11.1 8.89,-11.1 8.89,-10.11 13.5,-5.5 13.5,5.5 5.4,13.6 -5.4,13.6 -13.5,5.5 -13.5,-5.4 -10.6,-8.3 -8.9,-10 -8.9,-11.898 -3.375,-11.898 -3.375,-6.096 -2.833,-6.096 -2.833,-12.031 -3.233,-12.432 -8.9,-12.432 -9.301,-12.031 -9.301,-11.566 -16.637,-11.566
no net on Bottom Solder "NONET_L-01_P-001" (solid): -9.55,8.413 -6.686,11.278 6.325,11.278 9.617,8.413 5.882,5.428 -8.001,6.198 -9.55,7.747
no net on Bottom Solder "NONET_L-01_P-001" (solid): 8.118,-9.888 8.118,-10.763 3.822,-10.763 3.822,-7.166 5.588,-5.4 8.75,-5.4 9.75,-6.4 9.75,-8.256
no net on Bottom Solder "NONET_L-01_P-001" (solid): -6.12,-4.82 -3.189,-7.75 2.3,-7.75 2.3,-10.795 -2.431,-10.795 -2.431,-10.417 -3.148,-9.7 -8.3,-9.7 -9.65,-8.35
no net on Top Solder "NONET_L-01_P-001" (solid): 9.55,8.413 6.686,11.278 -6.325,11.278 -9.617,8.413 -5.882,5.428 8.001,6.198 9.55,7.747
no net on Top Solder "NONET_L-01_P-001" (solid): 6.12,-4.82 3.189,-7.75 -2.3,-7.75 -2.3,-10.8 2.431,-10.8 2.431,-10.417 3.148,-9.7 8.3,-9.7 9.65,-8.35
no net on Top Solder "NONET_L-01_P-001" (solid): -8.118,-9.888 -8.118,-10.763 -3.822,-10.763 -3.822,-7.166 -5.588,-5.4 -8.75,-5.4 -9.75,-6.4 -9.75,-8.256
no net on Bottom Paste "NONET_L-01_P-001" (solid): 8.118,-9.078 8.118,-10.763 3.822,-10.763 3.822,-7.95 6.372,-5.4 8.75,-5.4 9.75,-6.4 9.75,-7.446
no net on Bottom Paste "NONET_L-01_P-001" (solid): -6.403,-5.103 -3.756,-7.75 2.3,-7.75 2.3,-10.795 -2.431,-10.795 -2.431,-10.417 -3.148,-9.7 -7.5,-9.7 -9.25,-7.95

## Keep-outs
Keep-Out Layer:
  circle w0.254: c0,0 r7
  lines w0.254: -15.2,-23.6 -12.8,-23.6 ; -15.2,-23.5 -15.2,-19.8 -17,-19.8 -17,-11.1 -8.9,-11.1 -8.895,-10.155 cw(c0,0) 8.987,-10.074 ; -12.8,-23.5 -12.8,-19.8 ; -12.8,-19.9 -11.2,-19.9 ; -11.2,-23.6 -8.8,-23.6 ; -11.2,-23.5 -11.2,-19.8 ; -8.8,-23.5 -8.8,-19.8 ; -8.8,-19.9 -4.2,-19.9 ; -4.2,-23.6 -1.8,-23.6 ; -4.2,-23.5 -4.2,-19.8 ; -1.8,-23.5 -1.8,-19.8 -0.2,-19.8 -0.2,-23.5 ; -0.2,-23.6 2.2,-23.6 ; 2.2,-23.5 2.2,-19.8 5,-19.8 5,-23.5 ; 5,-23.6 13,-23.6 13,-19.613 16.987,-19.613 17,-11.1 9,-11.1 9,-10.1

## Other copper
Signal Layer 1:
  rectangle net SGND1: 14.072,-19.178 16.552,-16.485
  rectangle net SGND1: -16.51,-19.1 -4.9,-17.134
  rectangle net SGND1: 11.99,-18.3 15.4,-16.7

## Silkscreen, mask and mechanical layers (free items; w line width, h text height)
Top Overlay:
  text "T2" at -11.481,-0.406 h1.85
  text "PQ32,1+1" at 0,-12.827 h1.2
Bottom Overlay:
  text "T1" at 10.947,-0.229 h1.85
  text "B" at 6.325,-19.863 h1
  text "G" at 8.28,-19.863 h1
  text "A" at 10.312,-19.964 h1
  text "V" at 12.344,-19.964 h1
Top Paste:
  lines w1: -0.825,-8.661 ccw(c0,0) 8.7,0
  lines w4: -7.085,-7.407 cw(c0,0) 7.559,-6.922
Bottom Paste:
  lines w1: -8.7,0 ccw(c0,0) 0.825,-8.661
  lines w4: -7.559,-6.922 cw(c0,0) 7.085,-7.407
Top Solder:
  circle w0.05: c0,0 r7.74
  pour cut-out: 7.74,0 cw(c0,0) 0,-7.74 cw(c0,0) -7.74,0 cw(c0,0) 0,7.74 cw(c0,0)
  lines w1: -0.787,-8.263 ccw(c0,0) 8.3,0 cw(c0,0) -0.787,-8.263
  lines w5: -7.085,-7.407 cw(c0,0) -5.634,8.563 ; 5.724,8.503 cw(c0,0) 7.559,-6.922
Bottom Solder:
  circle w0.05: c0,0 r7.74
  pour cut-out: -7.74,0 ccw(c0,0) 0,-7.74 ccw(c0,0) 7.74,0 ccw(c0,0) 0,7.74 ccw(c0,0)
  lines w1: -8.3,0 ccw(c0,0) 0.787,-8.263
  lines w5: -7.559,-6.922 cw(c0,0) -5.724,8.503 ; 5.634,8.563 cw(c0,0) 7.085,-7.407
Mechanical 1:
  circle w0.254: c0,0 r7
  lines w0.254: -8.925,-10.129 cw(c0,0) -1.997,13.351 ; -8.9,-11.1 -17,-11.1 -17,-19.4 -15.2,-19.4 -15.2,-21.692 -12.8,-21.692 -12.8,-19.4 -11.2,-19.4 -11.2,-21.768 -8.8,-21.768 -8.8,-19.4 -4.2,-19.4 -4.2,-21.768 -1.8,-21.768 -1.8,-19.4 -0.2,-19.4 -0.2,-21.768 2.2,-21.768 2.2,-19.4 5,-19.4 5,-21.488 13,-21.488 13,-19.613 16.987,-19.613 17,-11.1 9,-11.1 9,-10.1 ; -8.895,-11.095 -8.895,-10.16 ; -1.99,13.3 ccw(c0,13.5) 1.986,13.264 ; 1.999,13.351 cw(c0,0) 8.987,-10.074
Mechanical 19:
  circle w0.1: c0,0 r7
  lines w0.1: -8.925,-10.129 cw(c0,0) 8.987,-10.074 ; -8.9,-10.1 -8.9,-14.9 -9,-15 -17.2,-15 -17.2,-29.5 17.2,-29.5 17.2,-15 9,-15 ; 9,-14.9 9,-10.1
  lines w0.3: -22,-19.5 22,-19.5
